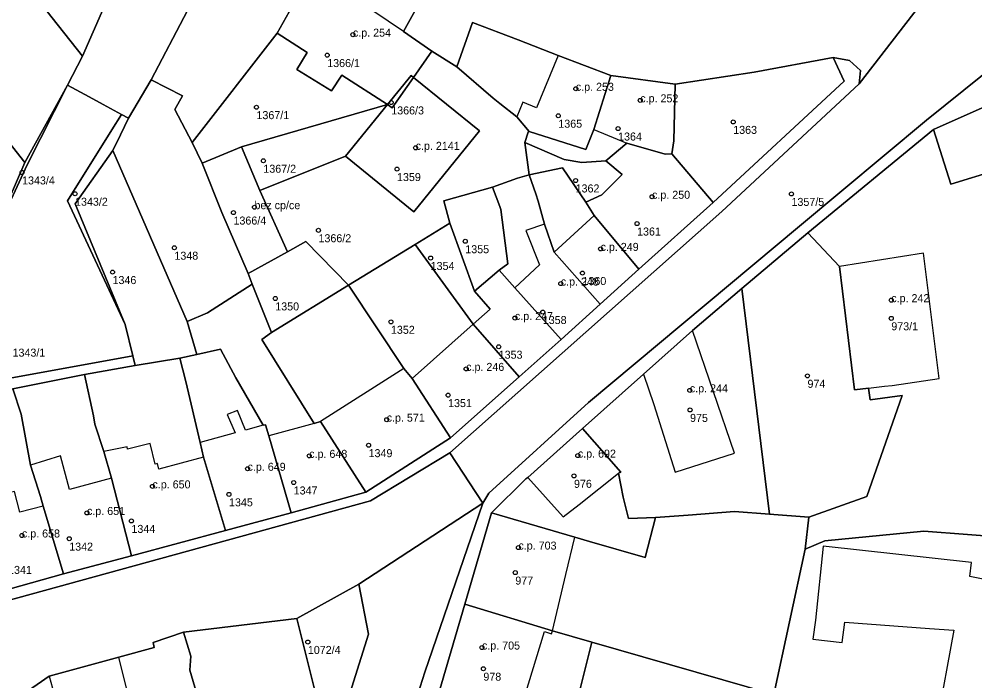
# Model space of a CAD drawing. Extents: x -878211 to -870363, y -1058464 to -1052522.
# Drawn here: x -875018.8 to -874899.4, y -1056399.5 to -1056316.9 of the extents above; entities that cross this region are included whole.
import ezdxf

# ---------------------------------------------------------------- set-up
doc = ezdxf.new("R2010")
doc.units = 0
for name, color, linetype in [('Definiční body', 7, 'Continuous'), ('Polygon budovy', 7, 'Continuous'), ('Polygon parcely', 7, 'Continuous')]:
    doc.layers.add(name, color=color, linetype=linetype)

msp = doc.modelspace()

# ---------------------------------------------------------------- linework, layer by layer
at = {"layer": 'Definiční body'}
for centre in [(-874977.07, -1056318.82994), (-874980.28, -1056321.38994), (-874949.22, -1056325.58994), (-874989.12, -1056327.88994), (-874972.28, -1056327.29994), (-874941.17, -1056327.02994), (-874951.41, -1056328.95994), (-874929.56, -1056329.72994), (-874943.94, -1056330.55994), (-874969.23, -1056332.95994), (-874988.26, -1056334.57994), (-875018.4, -1056336.03994), (-874971.56, -1056335.61994), (-874949.25, -1056337.03994), (-875011.78, -1056338.69994), (-874939.7, -1056339.06994), (-874922.28, -1056338.71994), (-874991.99, -1056341.04994), (-874989.37, -1056340.36994), (-874981.37, -1056343.25994), (-874941.57, -1056342.41994), (-874963.03, -1056344.62994), (-874999.37, -1056345.43994), (-874946.13, -1056345.57994), (-874967.36, -1056346.71994), (-875007.1, -1056348.47994), (-874948.39, -1056348.59994), (-874951.1, -1056349.90994), (-874986.77, -1056351.76994), (-874909.81, -1056351.97994), (-874956.83, -1056354.20994), (-874953.35, -1056353.46994), (-874972.32, -1056354.68994), (-874909.81, -1056354.24994), (-874958.86, -1056357.79994), (-874962.92, -1056360.55994), (-874920.28, -1056361.42994), (-874934.98, -1056363.23994), (-874965.18, -1056363.83994), (-874934.95, -1056365.68994), (-874972.85, -1056366.89994), (-874975.11, -1056370.08994), (-874982.53, -1056371.41994), (-874948.97, -1056371.38994), (-874990.23, -1056373.02994), (-874949.45, -1056373.91994), (-875002.11, -1056375.22994), (-874984.47, -1056374.74994), (-874992.55, -1056376.22994), (-875010.29, -1056378.54994), (-875004.74, -1056379.54994), (-875018.42, -1056381.35994), (-875012.51, -1056381.75994), (-874956.39, -1056382.86994), (-874956.78, -1056385.99994), (-874982.7, -1056394.65994), (-874960.95, -1056395.34994), (-874960.77, -1056397.99994)]:
    msp.add_circle(centre, 0.25, dxfattribs=at)
at = {"layer": 'Polygon budovy'}
for points in [[(-874970.75, -1056318.42), (-874981.99, -1056310.83), (-874985.03, -1056315.98), (-874986.52, -1056318.63), (-874982.78, -1056321.06), (-874984.09, -1056323.18), (-874979.76, -1056325.86), (-874978.44, -1056323.87), (-874972.76, -1056327.56), (-874969.81, -1056323.92), (-874969.5, -1056324.17), (-874967.21, -1056320.9)], [(-874944.84, -1056323.93), (-874951.41, -1056321.43), (-874954.14, -1056327.98), (-874955.83, -1056327.27), (-874956.6, -1056329.07), (-874955.07, -1056330.91), (-874947.99, -1056333.15), (-874946.97, -1056330.68)], [(-874972.76, -1056327.56), (-874978, -1056334.02), (-874969.44, -1056340.95), (-874961.26, -1056330.85), (-874969.5, -1056324.17), (-874969.81, -1056323.92)], [(-874946.97, -1056330.68), (-874942.85, -1056332.37), (-874938.05, -1056333.75), (-874937.23, -1056333.69), (-874936.98, -1056332.09), (-874936.83, -1056325), (-874944.84, -1056323.93)], [(-874904.55, -1056330.66), (-874902.38, -1056337.5), (-874896.66, -1056335.74), (-874892.58, -1056334.49), (-874887.08, -1056331.9), (-874891.71, -1056324.96)], [(-874947.99, -1056339.75), (-874946.91, -1056341.42), (-874941.35, -1056348.11), (-874932.06, -1056339.79), (-874937.23, -1056333.69), (-874938.05, -1056333.75), (-874942.85, -1056332.37), (-874945.49, -1056334.59), (-874943.45, -1056336.29), (-874945.96, -1056338.81)], [(-874990.97, -1056332.83), (-874995.92, -1056334.89), (-874993.46, -1056341.04), (-874990.15, -1056348.67), (-874985.26, -1056345.94), (-874988.68, -1056338.3)], [(-874946.91, -1056341.42), (-874951.94, -1056345.99), (-874946.18, -1056352.46), (-874941.35, -1056348.11)], [(-874953.76, -1056347.56), (-874956.83, -1056350.42), (-874951.06, -1056356.87), (-874946.18, -1056352.46), (-874951.94, -1056345.99), (-874953.12, -1056342.47), (-874955.46, -1056343.28)], [(-874903.83, -1056361.74), (-874905.8, -1056346.09), (-874916.29, -1056347.79), (-874914.41, -1056363.17), (-874912.67, -1056362.96), (-874910.66, -1056362.71), (-874909.71, -1056362.62)], [(-874959.94, -1056353.09), (-874962.05, -1056354.99), (-874956.3, -1056361.54), (-874951.06, -1056356.87), (-874956.83, -1056350.42), (-874958.8, -1056348.22), (-874961.89, -1056350.84)], [(-874962.05, -1056354.99), (-874969.65, -1056361.74), (-874964.89, -1056369.18), (-874956.3, -1056361.54)], [(-874940.77, -1056361.21), (-874939.48, -1056365.01), (-874936.8, -1056373.46), (-874929.4, -1056371.07), (-874934.66, -1056355.77)], [(-874981.11, -1056367.14), (-874975.44, -1056375.95), (-874964.89, -1056369.18), (-874969.65, -1056361.74), (-874970.69, -1056360.49)], [(-874984.8, -1056378.53), (-874987.56, -1056368.91), (-874988.01, -1056367.53), (-874988.27, -1056367.6), (-874990.47, -1056368.2), (-874991.47, -1056365.74), (-874992.79, -1056366.26), (-874991.78, -1056368.55), (-874996.16, -1056369.74), (-874995.74, -1056371.57), (-874992.97, -1056380.73)], [(-874981.92, -1056367.36), (-874987.56, -1056368.91), (-874984.8, -1056378.53), (-874975.44, -1056375.95), (-874981.11, -1056367.14)], [(-874955.21, -1056374.1), (-874950.79, -1056379.05), (-874948.79, -1056377.47), (-874943.91, -1056373.58), (-874943.6, -1056373.45), (-874948.4, -1056368.02)], [(-875005.28, -1056370.3), (-875008.2, -1056370.88), (-875007.22, -1056374.2), (-875004.72, -1056383.89), (-874992.97, -1056380.73), (-874995.74, -1056371.57), (-875001.31, -1056373.06), (-875001.48, -1056372.37), (-875001.78, -1056372.44), (-875002.41, -1056369.87), (-875005.21, -1056370.58)], [(-875013.6, -1056371.41), (-875017.34, -1056372.57), (-875016.09, -1056376.48), (-875015.77, -1056377.69), (-875013.23, -1056386.13), (-875004.72, -1056383.89), (-875007.22, -1056374.2), (-875012.49, -1056375.61)], [(-875015.77, -1056377.69), (-875018.66, -1056378.46), (-875019.36, -1056375.86), (-875021.14, -1056376.34), (-875021.51, -1056374.99), (-875023.38, -1056375.5), (-875024.19, -1056372.51), (-875025.45, -1056372.85), (-875024.72, -1056375.76), (-875023.7, -1056379.37), (-875021.27, -1056388.39), (-875013.23, -1056386.13)], [(-874952.14, -1056393.26), (-874950.47, -1056386.25), (-874949.34, -1056381.56), (-874959.76, -1056378.53), (-874963.08, -1056389.92)], [(-874919.29, -1056391.92), (-874919.61, -1056394.29), (-874915.96, -1056394.74), (-874915.61, -1056392.19), (-874905.02, -1056392.98), (-874901.98, -1056393.2), (-874904.11, -1056404.76), (-874906.24, -1056416.24), (-874898.07, -1056417.7), (-874895.86, -1056406.18), (-874894.55, -1056399.35), (-874892.45, -1056387.93), (-874896.72, -1056387.12), (-874896.52, -1056385.93), (-874897.95, -1056385.7), (-874898.12, -1056386.86), (-874899.99, -1056386.5), (-874899.81, -1056384.72), (-874918.34, -1056382.71)], [(-874966.7, -1056402.29), (-874956.82, -1056405.26), (-874955.88, -1056402.32), (-874954.2, -1056396.87), (-874953.14, -1056393.36), (-874952.26, -1056393.63), (-874952.14, -1056393.26), (-874963.08, -1056389.92)], [(-875015, -1056398.93), (-875012.5, -1056407.9), (-875007.67, -1056406.58), (-875007.36, -1056407.74), (-875005.13, -1056407.08), (-875005.43, -1056406.02), (-875004.05, -1056405.64), (-875006.33, -1056396.55)]]:
    msp.add_lwpolyline(points, close=True, dxfattribs=at)
at = {"layer": 'Polygon parcely'}
for points in [[(-875010.87, -1056321.51), (-875006.87, -1056312.35), (-875004.57, -1056306.52), (-875001.46, -1056298.36), (-875008.18, -1056295.76), (-875013.82, -1056300.32), (-875022.27, -1056307.12)], [(-875001.46, -1056298.36), (-875004.57, -1056306.52), (-875006.87, -1056312.35), (-875010.87, -1056321.51), (-875012.72, -1056325.15), (-875010.03, -1056326.6), (-875008.25, -1056327.56), (-875005.97, -1056328.79), (-875005.09, -1056329.27), (-875002.26, -1056324.46), (-874997.74, -1056315.82), (-874997.32, -1056315.06), (-874995.25, -1056311.85), (-874990.21, -1056302.54), (-874997.82, -1056299.69)], [(-874986.52, -1056318.63), (-874985.03, -1056315.98), (-874981.99, -1056310.83), (-874980.29, -1056307.87), (-874986.9, -1056304.35), (-874990.21, -1056302.54), (-874995.25, -1056311.85), (-874997.32, -1056315.06), (-874997.74, -1056315.82), (-875002.26, -1056324.46), (-874998.37, -1056326.48), (-874999.33, -1056328.19), (-874997.14, -1056332.31)], [(-874881.22, -1056310.9), (-874886.54, -1056301.59), (-874894.54, -1056305.09), (-874895.23, -1056303.94), (-874901.88, -1056307.12), (-874901.47, -1056308.26), (-874902.16, -1056309.87), (-874913.81, -1056324.98), (-874931, -1056340.89), (-874964.95, -1056371.04), (-874960.83, -1056377.33), (-874960.07, -1056376.07), (-874947.65, -1056364.74), (-874921.27, -1056342.74), (-874905.41, -1056329.51), (-874884.82, -1056312.95)], [(-875010.87, -1056321.51), (-875022.27, -1056307.12), (-875025.61, -1056309.81), (-875033.1, -1056315.81), (-875027.75, -1056322.53), (-875018.04, -1056334.77), (-875012.72, -1056325.15)], [(-874972.76, -1056327.56), (-874969.81, -1056323.92), (-874969.5, -1056324.17), (-874967.21, -1056320.9), (-874970.75, -1056318.42), (-874968.66, -1056314.69), (-874980.29, -1056307.87), (-874981.99, -1056310.83), (-874985.03, -1056315.98), (-874986.52, -1056318.63), (-874982.78, -1056321.06), (-874984.09, -1056323.18), (-874979.76, -1056325.86), (-874978.44, -1056323.87)], [(-875034.88, -1056335.04), (-875024.46, -1056348.23), (-875024.09, -1056348.7), (-875018.04, -1056334.77), (-875027.75, -1056322.53), (-875033.1, -1056315.81), (-875040.55, -1056321.74), (-875043.75, -1056324.31), (-875036.22, -1056333.29)], [(-874955.07, -1056330.91), (-874947.99, -1056333.15), (-874946.97, -1056330.68), (-874944.84, -1056323.93), (-874951.41, -1056321.43), (-874956.43, -1056319.48), (-874962.15, -1056317.3), (-874964.09, -1056322.83), (-874959.53, -1056326.75), (-874959.32, -1056326.93), (-874958.72, -1056327.41), (-874956.6, -1056329.07)], [(-874990.97, -1056332.83), (-874972.76, -1056327.56), (-874978.44, -1056323.87), (-874979.76, -1056325.86), (-874984.09, -1056323.18), (-874982.78, -1056321.06), (-874986.52, -1056318.63), (-874997.14, -1056332.31), (-874995.92, -1056334.89)], [(-874985.26, -1056345.94), (-874982.94, -1056344.65), (-874977.61, -1056350.1), (-874969.28, -1056345.01), (-874964.95, -1056342.35), (-874965.73, -1056339.59), (-874959.62, -1056337.87), (-874956.52, -1056336.74), (-874955.05, -1056336.31), (-874955.59, -1056332.28), (-874955.17, -1056331.01), (-874955.07, -1056330.91), (-874956.6, -1056329.07), (-874958.72, -1056327.41), (-874959.32, -1056326.93), (-874959.53, -1056326.75), (-874964.09, -1056322.83), (-874967.21, -1056320.9), (-874969.5, -1056324.17), (-874961.26, -1056330.85), (-874969.44, -1056340.95), (-874978, -1056334.02), (-874988.68, -1056338.3)], [(-874936.83, -1056325), (-874936.98, -1056332.09), (-874937.23, -1056333.69), (-874932.06, -1056339.79), (-874915.69, -1056324.63), (-874917.07, -1056321.68), (-874926.96, -1056323.52)], [(-874969.5, -1056324.17), (-874969.81, -1056323.92), (-874972.76, -1056327.56), (-874972.15, -1056327.96)], [(-874937.23, -1056333.69), (-874936.98, -1056332.09), (-874936.83, -1056325), (-874944.84, -1056323.93), (-874946.97, -1056330.68), (-874947.99, -1056333.15), (-874955.07, -1056330.91), (-874955.17, -1056331.01), (-874955.59, -1056332.28), (-874950.69, -1056334.43), (-874948.48, -1056334.78), (-874945.49, -1056334.59), (-874942.85, -1056332.37), (-874938.05, -1056333.75)], [(-875012.72, -1056325.15), (-875017.78, -1056335.1), (-875024.09, -1056348.7), (-875032.04, -1056362.61), (-875032.74, -1056364.05), (-875004.56, -1056358.93), (-875005.51, -1056355.03), (-875012.73, -1056339.57), (-875007.18, -1056330.72), (-875005.97, -1056328.79), (-875008.25, -1056327.56), (-875010.03, -1056326.6)], [(-875012.72, -1056325.15), (-875018.04, -1056334.77), (-875024.09, -1056348.7), (-875017.78, -1056335.1)], [(-875005.09, -1056329.27), (-875006.09, -1056331.32), (-875007.05, -1056333.29), (-874997.76, -1056354.63), (-874995.23, -1056353.56), (-874989.64, -1056349.97), (-874990.15, -1056348.67), (-874993.46, -1056341.04), (-874995.92, -1056334.89), (-874997.14, -1056332.31), (-874999.33, -1056328.19), (-874998.37, -1056326.48), (-875002.26, -1056324.46)], [(-874969.44, -1056340.95), (-874961.26, -1056330.85), (-874969.5, -1056324.17), (-874972.15, -1056327.96), (-874972.76, -1056327.56), (-874978, -1056334.02)], [(-874891.71, -1056324.96), (-874904.55, -1056330.66), (-874902.38, -1056337.5), (-874896.66, -1056335.74), (-874892.58, -1056334.49), (-874887.08, -1056331.9)], [(-874988.68, -1056338.3), (-874978, -1056334.02), (-874972.76, -1056327.56), (-874990.97, -1056332.83)], [(-875006.09, -1056331.32), (-875005.09, -1056329.27), (-875005.97, -1056328.79), (-875007.18, -1056330.72), (-875012.73, -1056339.57), (-875005.51, -1056355.03), (-875011.75, -1056339.97), (-875007.05, -1056333.29)], [(-874902.38, -1056337.5), (-874904.55, -1056330.66), (-874920.25, -1056343.56), (-874916.29, -1056347.79), (-874914.41, -1056363.17), (-874912.67, -1056362.96), (-874912.47, -1056364.43), (-874908.45, -1056363.89), (-874912.87, -1056376.5), (-874920.12, -1056379.07), (-874920.55, -1056383.05), (-874918.12, -1056382.02), (-874905.74, -1056380.82), (-874894.82, -1056381.67), (-874894.83, -1056381.48), (-874889.5, -1056381.99), (-874889.73, -1056366.76), (-874890.3, -1056365.2), (-874890.85, -1056355.65), (-874897.04, -1056344.18), (-874894.01, -1056343.19), (-874896.66, -1056335.74)], [(-874948.48, -1056334.78), (-874950.69, -1056334.43), (-874955.59, -1056332.28), (-874955.05, -1056336.31), (-874950.88, -1056335.44), (-874947.99, -1056339.75), (-874945.96, -1056338.81), (-874943.45, -1056336.29), (-874945.49, -1056334.59)], [(-874943.45, -1056336.29), (-874945.96, -1056338.81), (-874947.99, -1056339.75), (-874946.91, -1056341.42), (-874941.35, -1056348.11), (-874932.06, -1056339.79), (-874937.23, -1056333.69), (-874938.05, -1056333.75), (-874942.85, -1056332.37), (-874945.49, -1056334.59)], [(-874997.76, -1056354.63), (-875007.05, -1056333.29), (-875011.75, -1056339.97), (-875005.51, -1056355.03), (-875004.56, -1056358.93), (-875004.26, -1056360.14), (-874998.71, -1056359.2), (-874996.58, -1056358.76)], [(-874995.92, -1056334.89), (-874993.46, -1056341.04), (-874990.15, -1056348.67), (-874985.26, -1056345.94), (-874988.68, -1056338.3), (-874990.97, -1056332.83)], [(-874947.99, -1056339.75), (-874950.88, -1056335.44), (-874955.05, -1056336.31), (-874954.2, -1056338.72), (-874953.94, -1056339.63), (-874953.12, -1056342.47), (-874951.94, -1056345.99), (-874946.18, -1056352.46), (-874941.35, -1056348.11), (-874946.91, -1056341.42)], [(-874953.12, -1056342.47), (-874953.94, -1056339.63), (-874954.2, -1056338.72), (-874955.05, -1056336.31), (-874956.52, -1056336.74), (-874959.62, -1056337.87), (-874958.71, -1056340.28), (-874958.58, -1056340.66), (-874957.71, -1056347.43), (-874958.8, -1056348.22), (-874956.83, -1056350.42), (-874951.06, -1056356.87), (-874946.18, -1056352.46), (-874951.94, -1056345.99)], [(-874957.71, -1056347.43), (-874958.58, -1056340.66), (-874958.71, -1056340.28), (-874959.62, -1056337.87), (-874965.73, -1056339.59), (-874964.95, -1056342.35), (-874961.89, -1056350.84), (-874958.8, -1056348.22)], [(-874964.95, -1056342.35), (-874969.28, -1056345.01), (-874962.05, -1056354.99), (-874959.94, -1056353.09), (-874961.89, -1056350.84)], [(-874928.49, -1056350.54), (-874925.02, -1056378.69), (-874920.12, -1056379.07), (-874912.87, -1056376.5), (-874908.45, -1056363.89), (-874912.47, -1056364.43), (-874912.67, -1056362.96), (-874914.41, -1056363.17), (-874916.29, -1056347.79), (-874920.25, -1056343.56)], [(-874977.61, -1056350.1), (-874982.94, -1056344.65), (-874985.26, -1056345.94), (-874990.15, -1056348.67), (-874989.64, -1056349.97), (-874987.26, -1056356.02)], [(-874962.05, -1056354.99), (-874969.28, -1056345.01), (-874977.61, -1056350.1), (-874970.69, -1056360.49), (-874969.65, -1056361.74)], [(-874956.83, -1056350.42), (-874958.8, -1056348.22), (-874961.89, -1056350.84), (-874959.94, -1056353.09), (-874962.05, -1056354.99), (-874956.3, -1056361.54), (-874951.06, -1056356.87)], [(-874989.64, -1056349.97), (-874995.23, -1056353.56), (-874997.76, -1056354.63), (-874996.58, -1056358.76), (-874993.62, -1056358.11), (-874991.69, -1056361.68), (-874988.27, -1056367.6), (-874988.01, -1056367.53), (-874987.56, -1056368.91), (-874984.8, -1056378.53), (-874975.44, -1056375.95), (-874981.11, -1056367.14), (-874981.92, -1056367.36), (-874988.45, -1056356.91), (-874987.26, -1056356.02)], [(-874977.61, -1056350.1), (-874987.26, -1056356.02), (-874988.45, -1056356.91), (-874981.92, -1056367.36), (-874981.11, -1056367.14), (-874975.44, -1056375.95), (-874964.89, -1056369.18), (-874969.65, -1056361.74), (-874970.69, -1056360.49)], [(-874929.4, -1056378.36), (-874925.02, -1056378.69), (-874928.49, -1056350.54), (-874934.66, -1056355.77), (-874940.77, -1056361.21), (-874948.4, -1056368.02), (-874943.6, -1056373.45), (-874943.91, -1056373.58), (-874943.3, -1056376.56), (-874942.63, -1056379.24), (-874939.25, -1056379.13), (-874935.19, -1056378.83)], [(-874969.65, -1056361.74), (-874964.89, -1056369.18), (-874956.3, -1056361.54), (-874962.05, -1056354.99)], [(-874991.69, -1056361.68), (-874993.62, -1056358.11), (-874996.58, -1056358.76), (-874998.71, -1056359.2), (-874997.93, -1056362.13), (-874996.16, -1056369.74), (-874995.74, -1056371.57), (-874992.97, -1056380.73), (-874984.8, -1056378.53), (-874987.56, -1056368.91), (-874988.01, -1056367.53), (-874988.27, -1056367.6)], [(-875019.57, -1056363.03), (-875010.59, -1056361.24), (-875004.26, -1056360.14), (-875004.56, -1056358.93), (-875032.74, -1056364.05), (-875033.29, -1056365.17), (-875027.85, -1056364.34)], [(-874992.97, -1056380.73), (-874995.74, -1056371.57), (-874996.16, -1056369.74), (-874997.93, -1056362.13), (-874998.71, -1056359.2), (-875004.26, -1056360.14), (-875010.59, -1056361.24), (-875009.49, -1056366.43), (-875009.33, -1056367.45), (-875008.2, -1056370.88), (-875007.22, -1056374.2), (-875004.72, -1056383.89)], [(-875009.49, -1056366.43), (-875010.59, -1056361.24), (-875019.57, -1056363.03), (-875018.52, -1056366.2), (-875017.34, -1056372.57), (-875016.09, -1056376.48), (-875015.77, -1056377.69), (-875013.23, -1056386.13), (-875004.72, -1056383.89), (-875007.22, -1056374.2), (-875008.2, -1056370.88), (-875009.33, -1056367.45)], [(-875016.09, -1056376.48), (-875017.34, -1056372.57), (-875018.52, -1056366.2), (-875019.57, -1056363.03), (-875027.85, -1056364.34), (-875026.35, -1056369.47), (-875025.45, -1056372.85), (-875024.72, -1056375.76), (-875023.7, -1056379.37), (-875021.27, -1056388.39), (-875013.23, -1056386.13), (-875015.77, -1056377.69)], [(-874947.52, -1056382.09), (-874940.56, -1056384.12), (-874939.25, -1056379.13), (-874942.63, -1056379.24), (-874943.3, -1056376.56), (-874943.91, -1056373.58), (-874943.6, -1056373.45), (-874948.4, -1056368.02), (-874955.21, -1056374.1), (-874955.45, -1056374.28), (-874959.76, -1056378.53), (-874949.34, -1056381.56)], [(-874959.76, -1056378.53), (-874963.08, -1056389.92), (-874952.14, -1056393.26), (-874947.24, -1056394.66), (-874924.5, -1056401.21), (-874920.55, -1056383.05), (-874920.12, -1056379.07), (-874925.02, -1056378.69), (-874929.4, -1056378.36), (-874935.19, -1056378.83), (-874939.25, -1056379.13), (-874940.56, -1056384.12), (-874947.52, -1056382.09), (-874949.34, -1056381.56)], [(-874923.91, -1056412.98), (-874894.75, -1056420.85), (-874893.04, -1056416.51), (-874890.82, -1056408.96), (-874885.57, -1056399.58), (-874862.13, -1056399.47), (-874861.41, -1056393.71), (-874850.27, -1056392.72), (-874850.58, -1056385.39), (-874853.91, -1056385.5), (-874889.34, -1056382.25), (-874889.5, -1056381.99), (-874894.83, -1056381.48), (-874894.82, -1056381.67), (-874905.74, -1056380.82), (-874918.12, -1056382.02), (-874920.55, -1056383.05), (-874924.5, -1056401.21)], [(-874984.08, -1056391.71), (-874981.2, -1056403.23), (-874982.58, -1056412.24), (-874980.45, -1056410.63), (-874975.13, -1056393.67), (-874976.34, -1056387.44)], [(-874927.21, -1056413.07), (-874923.91, -1056412.98), (-874926.18, -1056408.98), (-874942.27, -1056402.9), (-874949.01, -1056401.83), (-874947.24, -1056394.66), (-874952.14, -1056393.26), (-874963.08, -1056389.92), (-874966.7, -1056402.29), (-874967.66, -1056405.55), (-874957.75, -1056408.4), (-874951.48, -1056409.42), (-874947.2, -1056410.02)], [(-874984.08, -1056391.71), (-874998.25, -1056393.44), (-874997.32, -1056396.44), (-874997.44, -1056398.16), (-874995.99, -1056403.11), (-874991.31, -1056401.83), (-874988.08, -1056412.56), (-874988.12, -1056414.34), (-874985.42, -1056414.69), (-874982.58, -1056412.24), (-874981.2, -1056403.23)], [(-875015, -1056398.93), (-875018.57, -1056401.39), (-875015.44, -1056411.27), (-875001.06, -1056406.74), (-875001.34, -1056404.9), (-874999.58, -1056404.88), (-874995.78, -1056403.81), (-874995.99, -1056403.11), (-874997.44, -1056398.16), (-874997.32, -1056396.44), (-874998.25, -1056393.44), (-875002.02, -1056394.71), (-875001.89, -1056395.35), (-875006.33, -1056396.55)], [(-874924.5, -1056401.21), (-874947.24, -1056394.66), (-874949.01, -1056401.83), (-874942.27, -1056402.9), (-874926.18, -1056408.98)]]:
    msp.add_lwpolyline(points, close=True, dxfattribs=at)
for points in [[(-874968.66, -1056314.69), (-874970.75, -1056318.42), (-874967.21, -1056320.9), (-874964.09, -1056322.83), (-874962.15, -1056317.3), (-874956.43, -1056319.48), (-874951.41, -1056321.43), (-874944.84, -1056323.93), (-874936.83, -1056325), (-874926.96, -1056323.52), (-874917.07, -1056321.68), (-874915.04, -1056322.04), (-874913.65, -1056323.29), (-874913.81, -1056324.98), (-874902.16, -1056309.87)], [(-874966.7, -1056402.29), (-874963.08, -1056389.92), (-874959.76, -1056378.53), (-874955.45, -1056374.28), (-874955.21, -1056374.1), (-874948.4, -1056368.02), (-874940.77, -1056361.21), (-874934.66, -1056355.77), (-874928.49, -1056350.54), (-874920.25, -1056343.56), (-874904.55, -1056330.66), (-874891.71, -1056324.96), (-874893.86, -1056321.68), (-874884.21, -1056314.45), (-874881.17, -1056312.72), (-874881.22, -1056310.9), (-874884.82, -1056312.95), (-874905.41, -1056329.51), (-874921.27, -1056342.74), (-874947.65, -1056364.74), (-874960.07, -1056376.07), (-874960.83, -1056377.33), (-874968.09, -1056398.43), (-874970.41, -1056405.77)], [(-875050.16, -1056397.7), (-874974.88, -1056377.04), (-874964.95, -1056371.04), (-874931, -1056340.89), (-874913.81, -1056324.98), (-874913.65, -1056323.29), (-874915.04, -1056322.04), (-874917.07, -1056321.68), (-874915.69, -1056324.63), (-874932.06, -1056339.79), (-874941.35, -1056348.11), (-874946.18, -1056352.46), (-874951.06, -1056356.87), (-874956.3, -1056361.54), (-874964.89, -1056369.18), (-874975.44, -1056375.95), (-874984.8, -1056378.53), (-874992.97, -1056380.73), (-875004.72, -1056383.89), (-875013.23, -1056386.13), (-875021.27, -1056388.39)], [(-875018.57, -1056401.39), (-875015, -1056398.93), (-875006.33, -1056396.55), (-875001.89, -1056395.35), (-875002.02, -1056394.71), (-874998.25, -1056393.44), (-874984.08, -1056391.71), (-874976.34, -1056387.44), (-874960.83, -1056377.33), (-874964.95, -1056371.04), (-874974.88, -1056377.04), (-875050.16, -1056397.7), (-875086.4, -1056394.69), (-875114.22, -1056383.98), (-875120.51, -1056377.36), (-875124.79, -1056378.79), (-875126.03, -1056378.37), (-875143.11, -1056370.16)], [(-874970.41, -1056405.77), (-874968.09, -1056398.43), (-874960.83, -1056377.33), (-874976.34, -1056387.44), (-874975.13, -1056393.67), (-874980.45, -1056410.63)]]:
    msp.add_lwpolyline(points, dxfattribs=at)

# ---------------------------------------------------------------- texts
at = {"layer": 'Definiční body'}
for s, p in [('c.p. 254', (-874977.07, -1056319.08)), ('1366/1', (-874980.28, -1056322.879)), ('c.p. 253', (-874949.22, -1056325.84)), ('c.p. 252', (-874941.17, -1056327.28)), ('1367/1', (-874989.12, -1056329.379)), ('1366/3', (-874972.28, -1056328.789)), ('1365', (-874951.41, -1056330.449)), ('1364', (-874943.94, -1056332.049)), ('1363', (-874929.56, -1056331.219)), ('c.p. 2141', (-874969.23, -1056333.21)), ('1367/2', (-874988.26, -1056336.069)), ('1343/4', (-875018.4, -1056337.529)), ('1359', (-874971.56, -1056337.109)), ('1362', (-874949.25, -1056338.529)), ('c.p. 250', (-874939.7, -1056339.32)), ('1343/2', (-875011.78, -1056340.189)), ('bez cp/ce', (-874989.37, -1056340.62)), ('1357/5', (-874922.28, -1056340.209)), ('1366/4', (-874991.99, -1056342.539)), ('1361', (-874941.57, -1056343.909)), ('1366/2', (-874981.37, -1056344.749)), ('1355', (-874963.03, -1056346.119)), ('c.p. 249', (-874946.13, -1056345.83)), ('1348', (-874999.37, -1056346.929)), ('1354', (-874967.36, -1056348.209)), ('1346', (-875007.1, -1056349.969)), ('c.p. 248', (-874951.1, -1056350.159)), ('1360', (-874948.39, -1056350.089)), ('c.p. 242', (-874909.81, -1056352.23)), ('1350', (-874986.77, -1056353.259)), ('c.p. 247', (-874956.83, -1056354.46)), ('1358', (-874953.35, -1056354.959)), ('973/1', (-874909.81, -1056355.739)), ('1352', (-874972.32, -1056356.179)), ('1343/1', (-875019.59, -1056359.029)), ('1353', (-874958.86, -1056359.289)), ('c.p. 246', (-874962.92, -1056360.81)), ('974', (-874920.28, -1056362.919)), ('c.p. 244', (-874934.98, -1056363.49)), ('1351', (-874965.18, -1056365.329)), ('c.p. 571', (-874972.85, -1056367.149)), ('975', (-874934.95, -1056367.179)), ('c.p. 648', (-874982.53, -1056371.669)), ('1349', (-874975.11, -1056371.579)), ('c.p. 692', (-874948.97, -1056371.639)), ('c.p. 649', (-874990.23, -1056373.28)), ('c.p. 650', (-875002.11, -1056375.48)), ('1347', (-874984.47, -1056376.239)), ('976', (-874949.45, -1056375.409)), ('c.p. 651', (-875010.29, -1056378.8)), ('1345', (-874992.55, -1056377.719)), ('1344', (-875004.74, -1056381.039)), ('c.p. 658', (-875018.42, -1056381.61)), ('1342', (-875012.51, -1056383.249)), ('c.p. 703', (-874956.39, -1056383.12)), ('1341', (-875020.15, -1056386.159)), ('977', (-874956.78, -1056387.489)), ('1072/4', (-874982.7, -1056396.149)), ('c.p. 705', (-874960.95, -1056395.6)), ('978', (-874960.77, -1056399.489))]:
    msp.add_text(s, height=0.999996, dxfattribs=at).set_placement(p)

doc.saveas('drawing.dxf')
